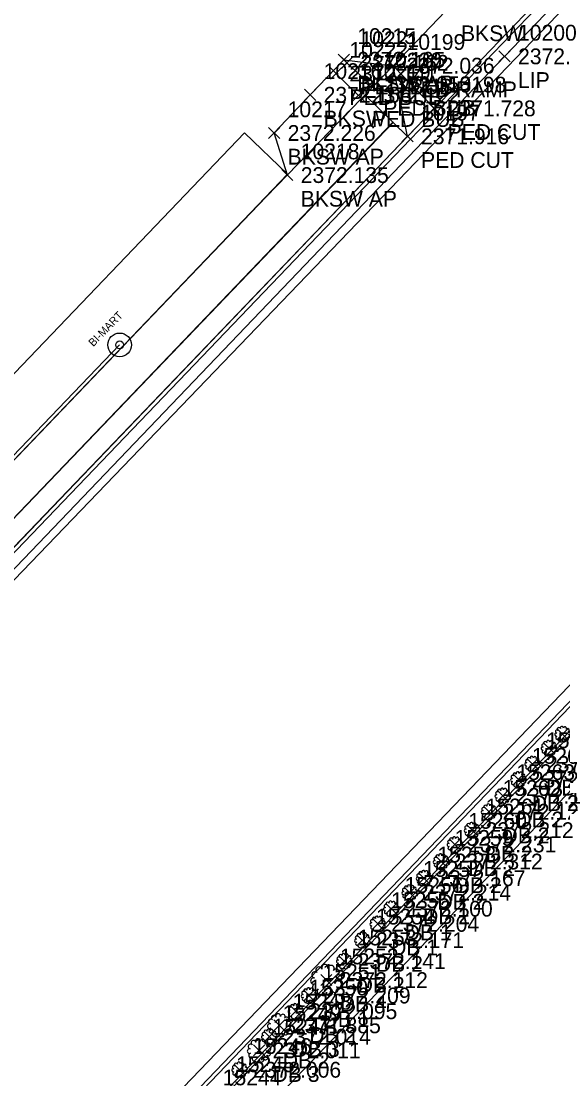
# Model space of a CAD drawing. Extents: x 2377639 to 2379738, y 729875 to 732734.
# Drawn here: x 2378522.8 to 2378591.5, y 730712.2 to 730846.3 of the extents above; entities that cross this region are included whole.
import ezdxf

# ---------------------------------------------------------------- set-up
doc = ezdxf.new("R2010")
doc.units = 0
for name, color, linetype in [('Default', 7, 'Continuous'), ('TOPO_CURBGTR_Back-of-Curb', 7, 'Continuous'), ('TOPO_CURBGTR_Face-of-Curb', 7, 'Continuous'), ('TOPO_CURBGTR_Lip-of-Gutter', 7, 'Continuous'), ('TOPO_DATA_Elevations', 7, 'Continuous'), ('TOPO_DATA_Notes', 7, 'Continuous'), ('TOPO_ELEC_Cable_Overhead-Exist', 7, 'Continuous'), ('TOPO_LNDSCP_Misc', 7, 'Continuous'), ('TOPO_LNDSCP_Tree', 7, 'Continuous'), ('TOPO_MISC_Flat-Asphalt', 7, 'Continuous'), ('TOPO_SIGNS_Post-Single', 7, 'Continuous'), ('TOPO_STORM_Line-Other', 7, 'Continuous'), ('TOPO_SW_Back', 7, 'Continuous'), ('TOPO_WTRUTIL_Line', 7, 'Continuous')]:
    doc.layers.add(name, color=color, linetype=linetype)

# ---------------------------------------------------------------- blocks, each defined once
blk = doc.blocks.new('DB_1')
at = {"layer": 'Default'}
for centre, radius, start, end in [((-0.0592, 0.0812), 0.0254, 16.78226, 235.0388), ((-0.0121, 0.0998), 0.0254, 347.98226, 206.2388), ((0.0381, 0.0934), 0.0254, 319.18226, 177.4388), ((0.079, 0.0636), 0.0254, 290.38226, 148.6388), ((-0.1011, -0.0074), 0.0254, 74.38226, 292.6388), ((-0.0916, 0.0423), 0.0254, 45.58226, 263.8388), ((0, 0), 0.00318, 0, 180), ((0, 0), 0.00318, 180, 0), ((0.1005, 0.0177), 0.0254, 261.58226, 119.8388), ((-0.0856, -0.0556), 0.0254, 103.18226, 321.4388), ((-0.0487, -0.0903), 0.0254, 131.98226, 278.46009), ((0.07, -0.0755), 0.0254, 203.98226, 62.2388), ((0.0972, -0.0328), 0.0254, 232.78226, 91.0388), ((-0.025, -0.0997), 0.0254, 218.16097, 4.6388), ((0.0256, -0.0998), 0.0254, 175.18226, 33.4388)]:
    blk.add_arc(centre, radius, start, end, dxfattribs=at)

msp = doc.modelspace()

# ---------------------------------------------------------------- linework, layer by layer
at = {"layer": 'TOPO_CURBGTR_Back-of-Curb'}
for points in [[(2378796.95, 731066.54), (2378792.22, 731061.65), (2378780.11, 731049.06), (2378765.8, 731034.16), (2378729.83, 730996.57), (2378708.78, 730974.71), (2378675.54, 730940.1), (2378596.07, 730857.01), (2378571.8, 730831.72), (2378484.65, 730740.78), (2378451.54, 730706.2), (2378383.47, 730635.07)], [(2378428.64, 730588.82), (2378465.5, 730627.29), (2378502.36, 730665.57), (2378506, 730669.31), (2378527.48, 730691.63), (2378605.98, 730773.58), (2378608.94, 730776.83)]]:
    msp.add_lwpolyline(points, dxfattribs=at)
at = {"layer": 'TOPO_CURBGTR_Face-of-Curb'}
for points in [[(2378797.32, 731066.2), (2378792.58, 731061.31), (2378780.47, 731048.72), (2378766.16, 731033.81), (2378730.19, 730996.23), (2378709.14, 730974.36), (2378675.9, 730939.76), (2378596.44, 730856.66), (2378572.16, 730831.38), (2378485.01, 730740.44), (2378451.9, 730705.86), (2378383.83, 730634.72)], [(2378428.28, 730589.17), (2378465.14, 730627.64), (2378502, 730665.92), (2378505.64, 730669.66), (2378527.12, 730691.97), (2378605.61, 730773.92), (2378608.57, 730777.17)]]:
    msp.add_lwpolyline(points, dxfattribs=at)
at = {"layer": 'TOPO_CURBGTR_Lip-of-Gutter'}
for points in [[(2378797.98, 731065.07), (2378794.67, 731061.59), (2378781.68, 731047.95), (2378751.07, 731015.98), (2378690.75, 730953), (2378584.09, 730841.86), (2378466.86, 730719.3), (2378390.08, 730639.26), (2378384.85, 730633.62), (2378384.85, 730633.62)], [(2378609, 730779.64), (2378604.75, 730775.02), (2378431.05, 730594.21), (2378426.07, 730588.91)]]:
    msp.add_lwpolyline(points, dxfattribs=at)
at = {"layer": 'TOPO_DATA_Elevations'}
for p, q in [((2378563.01, 730840.72), (2378564.42, 730842.13)), ((2378563.01, 730842.13), (2378564.42, 730840.72)), ((2378583.38, 730841.16), (2378584.8, 730842.57)), ((2378583.38, 730842.57), (2378584.8, 730841.16)), ((2378563.41, 730840.33), (2378564.83, 730841.74)), ((2378563.41, 730841.74), (2378564.83, 730840.33)), ((2378569.26, 730839.97), (2378570.67, 730841.39)), ((2378569.26, 730841.39), (2378570.67, 730839.97)), ((2378562.01, 730838.98), (2378563.42, 730840.39)), ((2378562.01, 730840.39), (2378563.42, 730838.98)), ((2378566.31, 730837.62), (2378567.72, 730839.03)), ((2378566.31, 730839.03), (2378567.72, 730837.62)), ((2378558.74, 730836.28), (2378560.16, 730837.7)), ((2378558.74, 730837.7), (2378560.16, 730836.28)), ((2378564.87, 730836.21), (2378566.28, 730837.63)), ((2378564.87, 730837.63), (2378566.28, 730836.21)), ((2378574.46, 730834.57), (2378575.88, 730835.98)), ((2378574.46, 730835.98), (2378575.88, 730834.57)), ((2378554.19, 730831.45), (2378555.6, 730832.86)), ((2378554.19, 730832.86), (2378555.6, 730831.45)), ((2378571.09, 730831.02), (2378572.51, 730832.43)), ((2378571.09, 730832.43), (2378572.51, 730831.02)), ((2378555.85, 730826.11), (2378557.26, 730827.52)), ((2378555.85, 730827.52), (2378557.26, 730826.11)), ((2378590.73, 730755.22), (2378592.14, 730756.63)), ((2378590.73, 730756.63), (2378592.14, 730755.22)), ((2378589, 730753.46), (2378590.42, 730754.87)), ((2378589, 730754.87), (2378590.42, 730753.46)), ((2378586.93, 730751.43), (2378588.34, 730752.84)), ((2378586.93, 730752.84), (2378588.34, 730751.43)), ((2378585.12, 730749.46), (2378586.54, 730750.88)), ((2378585.12, 730750.88), (2378586.54, 730749.46)), ((2378583.17, 730747.39), (2378584.58, 730748.81)), ((2378583.17, 730748.81), (2378584.58, 730747.39)), ((2378581.42, 730745.38), (2378582.83, 730746.8)), ((2378581.42, 730746.8), (2378582.83, 730745.38)), ((2378579.27, 730743.04), (2378580.68, 730744.45)), ((2378579.27, 730744.45), (2378580.68, 730743.04)), ((2378577.08, 730741.22), (2378578.49, 730742.64)), ((2378577.08, 730742.64), (2378578.49, 730741.22)), ((2378575.34, 730739.06), (2378576.76, 730740.48)), ((2378575.34, 730740.48), (2378576.76, 730739.06)), ((2378573.17, 730736.95), (2378574.58, 730738.36)), ((2378573.17, 730738.36), (2378574.58, 730736.95)), ((2378571.35, 730735.13), (2378572.76, 730736.54)), ((2378571.35, 730736.54), (2378572.76, 730735.13)), ((2378569.02, 730733.08), (2378570.43, 730734.49)), ((2378569.02, 730734.49), (2378570.43, 730733.08)), ((2378567.29, 730731.16), (2378568.71, 730732.58)), ((2378567.29, 730732.58), (2378568.71, 730731.16)), ((2378565.38, 730729.08), (2378566.79, 730730.49)), ((2378565.38, 730730.49), (2378566.79, 730729.08)), ((2378563.06, 730726.43), (2378564.48, 730727.85)), ((2378563.06, 730727.85), (2378564.48, 730726.43)), ((2378560.79, 730724.04), (2378562.21, 730725.45)), ((2378560.79, 730725.45), (2378562.21, 730724.04)), ((2378558.6, 730722.07), (2378560.02, 730723.49)), ((2378558.6, 730723.49), (2378560.02, 730722.07)), ((2378556.93, 730720.08), (2378558.34, 730721.5)), ((2378556.93, 730721.5), (2378558.34, 730720.08)), ((2378554.84, 730718.3), (2378556.25, 730719.71)), ((2378554.84, 730719.71), (2378556.25, 730718.3)), ((2378553.57, 730716.86), (2378554.98, 730718.27)), ((2378553.57, 730718.27), (2378554.98, 730716.86)), ((2378552.28, 730715.12), (2378553.69, 730716.53)), ((2378552.28, 730716.53), (2378553.69, 730715.12)), ((2378549.8, 730712.66), (2378551.22, 730714.07)), ((2378549.8, 730714.07), (2378551.22, 730712.66))]:
    msp.add_line(p, q, dxfattribs=at)
at = {"layer": 'TOPO_ELEC_Cable_Overhead-Exist'}
msp.add_line((2378457.25, 730724.11), (2378535.31, 730805.28), dxfattribs=at)
at = {"layer": 'TOPO_LNDSCP_Misc'}
msp.add_lwpolyline([(2378487.03, 730754.25), (2378556.6, 730826.93), (2378551.15, 730832.15), (2378481.58, 730759.47)], close=True, dxfattribs=at)
at = {"layer": 'TOPO_MISC_Flat-Asphalt'}
msp.add_lwpolyline([(2378482.84, 730742.51), (2378569.94, 730833.5), (2378571.8, 730831.72), (2378484.69, 730740.74)], close=True, dxfattribs=at)
at = {"layer": 'TOPO_SIGNS_Post-Single'}
for radius in [1.5, 0.5]:
    msp.add_circle((2378535.31, 730805.28), radius, dxfattribs=at)
at = {"layer": 'TOPO_STORM_Line-Other'}
for q in [(2378187, 730332.08), (2378188.38, 730333.53)]:
    msp.add_line((2378608.31, 730773.03), q, dxfattribs=at)
at = {"layer": 'TOPO_SW_Back'}
for p, q in [((2378569.96, 730840.68), (2378575.19, 730835.25)), ((2378571.8, 730831.72), (2378566.37, 730836.97))]:
    msp.add_line(p, q, dxfattribs=at)
for points in [[(2378571.8, 730831.72), (2378569.96, 730840.68), (2378587.08, 730858.58), (2378596.07, 730857.01)], [(2378476.31, 730743.06), (2378553.89, 730824.05), (2378569.96, 730840.68)], [(2378556.56, 730826.81), (2378554.9, 730832.15), (2378559.45, 730836.99), (2378563.72, 730841.43), (2378569.96, 730840.68)], [(2378570, 730833.46), (2378569.99, 730833.46), (2378482.84, 730742.51), (2378482.84, 730742.51)], [(2378532.38, 730696.74), (2378534.18, 730695.01), (2378607.54, 730771.6), (2378605.7, 730773.28)], [(2378474.98, 730627.55), (2378508.09, 730660.21), (2378532.77, 730686.32), (2378606.65, 730763.63), (2378611.23, 730768.23), (2378618.35, 730761.5)]]:
    msp.add_lwpolyline(points, dxfattribs=at)
msp.add_lwpolyline([(2378567.01, 730838.33), (2378564.12, 730841.04), (2378562.71, 730839.68), (2378565.57, 730836.92)], close=True, dxfattribs=at)
at = {"layer": 'TOPO_WTRUTIL_Line'}
msp.add_line((2378391.81, 730640.09), (2378830.45, 731096.49), dxfattribs=at)

# ---------------------------------------------------------------- block references
at = {"layer": 'TOPO_LNDSCP_Tree'}
for p, xscale, yscale in [((2378591.44, 730755.93), 7.8740000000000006, 7.8740000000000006), ((2378589.71, 730754.16), 7.8740000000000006, 7.8740000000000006), ((2378587.64, 730752.14), 7.8740000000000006, 7.8740000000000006), ((2378585.83, 730750.17), 7.8740000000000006, 7.8740000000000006), ((2378583.87, 730748.1), 7.8740000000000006, 7.8740000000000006), ((2378582.12, 730746.09), 7.8740000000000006, 7.8740000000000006), ((2378579.97, 730743.75), 7.8740000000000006, 7.8740000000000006), ((2378577.79, 730741.93), 7.8740000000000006, 7.8740000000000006), ((2378576.05, 730739.77), 7.8740000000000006, 7.8740000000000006), ((2378573.88, 730737.66), 7.8740000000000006, 7.8740000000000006), ((2378572.06, 730735.83), 7.8740000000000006, 7.8740000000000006), ((2378569.73, 730733.79), 7.8740000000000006, 7.8740000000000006), ((2378568, 730731.87), 7.8740000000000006, 7.8740000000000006), ((2378566.08, 730729.79), 7.8740000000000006, 7.8740000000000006), ((2378563.77, 730727.14), 7.8740000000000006, 7.8740000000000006), ((2378561.5, 730724.74), 15.748000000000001, 15.748000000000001), ((2378559.31, 730722.78), 7.8740000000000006, 7.8740000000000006), ((2378557.64, 730720.79), 7.8740000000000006, 7.8740000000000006), ((2378555.54, 730719), 11.811, 11.811), ((2378554.27, 730717.56), 7.8740000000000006, 7.8740000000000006), ((2378552.98, 730715.83), 11.811, 11.811), ((2378550.51, 730713.37), 7.8740000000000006, 7.8740000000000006)]:
    msp.add_blockref('DB_1', p, dxfattribs=dict(at, xscale=xscale, yscale=yscale))

# ---------------------------------------------------------------- texts
at = {"layer": 'TOPO_DATA_Elevations'}
for s, p in [('BKSW', (2378578.57, 730843.79)), ('10200', (2378585.8, 730843.86)), ('10215', (2378565.42, 730843.43)), ('10221', (2378565.83, 730843.04)), ('10199', (2378571.67, 730842.68)), ('10222', (2378564.42, 730841.68)), ('2372.165', (2378565.42, 730840.43)), ('2372.162', (2378565.83, 730840.04)), ('10220', (2378568.72, 730840.33)), ('2372.036', (2378585.8, 730840.86)), ('10216', (2378561.16, 730838.99)), ('2372.141', (2378564.42, 730838.68)), ('10219', (2378567.28, 730838.92)), ('2372.036', (2378571.67, 730839.68)), ('BKSW AP', (2378565.42, 730837.43)), ('2372.053', (2378568.72, 730837.33)), ('10198', (2378576.88, 730837.27)), ('LIP', (2378585.8, 730837.86)), ('2372.166', (2378561.16, 730835.99)), ('PED BUB', (2378565.83, 730837.04)), ('2372.122', (2378567.28, 730835.92)), ('PED RAMP', (2378571.67, 730836.68)), ('PED BUB', (2378564.42, 730835.68)), ('10217', (2378556.6, 730834.15)), ('PED BUB', (2378568.72, 730834.33)), ('10197', (2378573.51, 730833.72)), ('2371.728', (2378576.88, 730834.27)), ('BKSW', (2378561.16, 730832.99)), ('PED BUB', (2378567.28, 730832.92)), ('2372.226', (2378556.6, 730831.15)), ('2371.916', (2378573.51, 730830.72)), ('PED CUT', (2378576.88, 730831.27)), ('BKSW AP', (2378556.6, 730828.15)), ('10218', (2378558.26, 730828.81)), ('PED CUT', (2378573.51, 730827.72)), ('2372.135', (2378558.26, 730825.81)), ('BKSW AP', (2378558.26, 730822.81)), ('15265', (2378589.34, 730754.14)), ('15264', (2378587.54, 730752.17)), ('15263', (2378585.58, 730750.1)), ('2372.117', (2378589.34, 730751.14)), ('2372.215', (2378587.54, 730749.17)), ('15262', (2378583.83, 730748.09)), ('DB 2', (2378589.34, 730748.14)), ('2372.192', (2378585.58, 730747.1)), ('DB 2', (2378587.54, 730746.17)), ('15261', (2378581.68, 730745.75)), ('2372.123', (2378583.83, 730745.09)), ('15260', (2378579.49, 730743.93)), ('DB 2', (2378585.58, 730744.1)), ('2372.212', (2378581.68, 730742.75)), ('DB 2', (2378583.83, 730742.09)), ('15259', (2378577.76, 730741.77)), ('2372.231', (2378579.49, 730740.93)), ('15258', (2378575.58, 730739.66)), ('DB 2', (2378581.68, 730739.75)), ('15257', (2378573.76, 730737.83)), ('2372.312', (2378577.76, 730738.77)), ('DB 2', (2378579.49, 730737.93)), ('2372.167', (2378575.58, 730736.66)), ('15256', (2378571.43, 730735.79)), ('DB 2', (2378577.76, 730735.77)), ('15255', (2378569.71, 730733.87)), ('2372.214', (2378573.76, 730734.83)), ('2372.100', (2378571.43, 730732.79)), ('DB 2', (2378575.58, 730733.66)), ('15254', (2378567.79, 730731.79)), ('DB 2', (2378573.76, 730731.83)), ('2372.204', (2378569.71, 730730.87)), ('DB 1', (2378571.43, 730729.79)), ('15253', (2378565.48, 730729.14)), ('2372.171', (2378567.79, 730728.79)), ('DB 1', (2378569.71, 730727.87)), ('15252', (2378563.21, 730726.74)), ('2372.141', (2378565.48, 730726.14)), ('DB 2', (2378567.79, 730725.79)), ('15251', (2378561.02, 730724.78)), ('2372.112', (2378563.21, 730723.74)), ('DB 2', (2378565.48, 730723.14)), ('15250', (2378559.34, 730722.79)), ('2372.209', (2378561.02, 730721.78)), ('15248', (2378557.25, 730721)), ('DB 4', (2378563.21, 730720.74)), ('15249', (2378555.98, 730719.56)), ('2372.095', (2378559.34, 730719.79)), ('15247', (2378554.69, 730717.83)), ('2371.885', (2378557.25, 730718)), ('DB 1', (2378561.02, 730718.78)), ('2372.014', (2378555.98, 730716.56)), ('DB 2', (2378559.34, 730716.79)), ('15246', (2378552.22, 730715.37)), ('DB 3', (2378557.25, 730715)), ('2372.011', (2378554.69, 730714.83)), ('15245', (2378550.06, 730713.07)), ('2372.006', (2378552.22, 730712.37)), ('DB 2', (2378555.98, 730713.56)), ('15244', (2378548.38, 730711.4)), ('DB 3', (2378554.69, 730711.83))]:
    msp.add_text(s, height=2, dxfattribs=at).set_placement(p)
at = {"layer": 'TOPO_DATA_Notes'}
msp.add_text('BI-MART', height=1, rotation=45.6929, dxfattribs=at).set_placement((2378531.97, 730804.99))

doc.saveas('drawing.dxf')
